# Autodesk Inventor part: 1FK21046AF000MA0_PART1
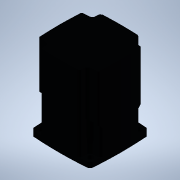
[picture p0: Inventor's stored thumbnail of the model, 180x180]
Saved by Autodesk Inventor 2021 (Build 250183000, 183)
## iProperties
Created: 2025-04
Part Number: 1FK21046AF000MA0_PART1
Material: Generic
Catalog Web Link: www.3dfindit.com
Description: -Servo synchronous motor
Document SubType Name: Modeling
Designer: psAdmin
Mass: 575.884 g
Surface Area: 489.738 cm^2
Volume: 575.884 cm^3
Density: 1 g/cm^3
Appearance: PSOLRGB-176-176-176
Category: PARTsolutions
Title: 1FK21046AF000MA0_PART1
Author: Cadenas PARTsolutions
Comments: Servo synchronous motor
Sending System: PARTsolutions
Preprocessor: ST-DEVELOPER v19.3
PSOL_IDENT_0: {$CADENAS_DATA/23d-libs/siemens_ag/_cat_/1c/1f/1fk21046af000ma0.prj},213 {VTYP=3D},{NB=1FK21046AF000
PSOL_IDENT_1: MA0_PART1},{LINA=1FK21046AF000MA0_PART1},{NN=1FK21046AF000MA0_PART1},{NOPRJ=TRUE},{DATE=19.08.2025 1
PSOL_IDENT_2: 4:00:28},{GEOMDATE=30.07.2025 02:02:08},{VERSION=},{LINEID=10},{WBVAR=},{WBNUMERIC=}  {NB=1FK21046AF
PSOL_IDENT_3: 000MA0_PART1},{LINA=1FK21046AF000MA0_PART1},{KT=DUMMY},{PREVIEW=../../../_pool_/cb/72/p_d211_xx_0043
PSOL_IDENT_4: 4j.png},{DESCSHORT=SIMOTICS S-1FK2 HD, SINAMICS S210 3AC 400V-480V, 3.2 Nm, 3000 rpm},{DESCLONG=SIMO
PSOL_IDENT_5: TICS S-1FK2 HD servo motor M0=3.2 Nm; PN = 1 kW at nN=3000 rpm (380-480 V); PN = 0.5 kW at nN=1500 r
PSOL_IDENT_6: pm (200-240 V); degree of protection IP64; cylindrical shaft D19x40mm; absolute encoder 22-bit + 12-
PSOL_IDENT_7: bit multiturn (encoder AM22DQC); with OCC interface; plug size M17, rotatable; SIMOTICS S-1FK2 servo
PSOL_IDENT_8: motorfor a wide range of uses in industrial environments. SIMOTICS S‑1FK2 servomotors are compact sy
PSOL_IDENT_9: nchronous motors with a high dynamic performance that set themselves apart as a result of their high
PSOL_IDENT_10: power density, degree of protection and overload capability. The motors are available in two varian
PSOL_IDENT_11: ts: as High Dynamic variant (highest dynamic performance as a result of the low intrinsic moment of
PSOL_IDENT_12: inertia for applications demanding a high dynamic performance with low moved masses) - and as Compac
PSOL_IDENT_13: t variant (precise and stable closed-loop control for medium up to large moved masses as a result of
PSOL_IDENT_14: a medium intrinsic moment of inertia). SIMOTICSS‑1FK2 servomotors fully exploit their strengths in
PSOL_IDENT_15: a system with the SINAMICSS210 frequency converter and simple connection using the one cable connect
PSOL_IDENT_16: ion (OCC). Advantages include the short control and positioning times, fast and precise correction o
PSOL_IDENT_17: f disturbing quantities as well as stable control with a high dynamic performance. The servo motors
PSOL_IDENT_18: can be configured to address a wide range of requirements. For example with and without holding brak
PSOL_IDENT_19: e, IP64 or IP65 degree of protection, singleturn or multiturn absolute encoders - to name just a few
PSOL_IDENT_20: . Further, the servomotors are available in different shaft heights extending from 20 to 100. A shaf
PSOL_IDENT_21: t sealing ring is available to achieve an IP65 degree of protection and for subsequent mounting at t
PSOL_IDENT_22: he motor or as spare part. SIMOTICS - the optimum motor for each and every motion control applicatio
PSOL_IDENT_23: n.},{INTNO=195125049666},{SUPPLIERALTNO=1FK2104-6AF00-0MA0},{MANUID=1FK21046AF000MA0},{MANUNAME=Siem
PSOL_IDENT_24: ens},{MANUTYPEDESC=Synchronous motor 1FK2-HD 3.2 NM},{AAU732=SIMOTICS},{AAO057=S-1FK2},{AAU734=SIMOT
PSOL_IDENT_25: ICS S-1FK2 HD servo motor M0=3.2 Nm; PN = 1 kW at nN=3000 rpm (380-480 V); PN = 0.5 kW at nN=1500 rp
PSOL_IDENT_26: m (200-240 V); degree of protection IP64; cylindrical shaft D19x40mm; absolute encoder 22-bit + 12-b
PSOL_IDENT_27: it multiturn (encoder AM22DQC); with OCC interface; plug size M17, rotatable;},{AAW338=Synchronous m
PSOL_IDENT_28: otor 1FK2-HD 3.2 NM},{AAO742=SIMOTICS},{AAO663=4042948694374},{NOCUPEROU=1},{PRICEQUANTITY=1},{QUANT
PSOL_IDENT_29: ITYMIN=1},{QUANTITYINT=1},{CTN=85015220},{COO=DE},{AAO676=1FK2104-6AF00-0MA0},{AAO677=Siemens AG},{O
PSOL_IDENT_30: RDERUNIT=C62},{CONTENTUNIT=C62}
NB: 1FK21046AF000MA0_PART1
NT: Servo synchronous motor
NBSYN: $MANUID._PART1
LINA: 1FK21046AF000MA0_PART1
CATALOG: SIEMENS
PREVIEW: ../../../_pool_/cb/72/p_d211_xx_00434j.png
DESCSHORT: SIMOTICS S-1FK2 HD, SINAMICS S210 3AC 400V-480V, 3.2 Nm, 3000 rpm
DESCLONG: SIMOTICS S-1FK2 HD servo motor M0=3.2 Nm; PN = 1 kW at nN=3000 rpm (380-480 V); PN = 0.5 kW at nN=1500 rpm (200-240 V); degree of protection IP64; cylindrical s
INTNO: 195125049666
SUPPLIERALTNO: 1FK2104-6AF00-0MA0
MANUID: 1FK21046AF000MA0
MANUNAME: Siemens
MANUTYPEDESC: Synchronous motor 1FK2-HD 3.2 NM
AAU732: SIMOTICS
AAO057: S-1FK2
AAU734: SIMOTICS S-1FK2 HD servo motor M0=3.2 Nm; PN = 1 kW at nN=3000 rpm (380-480 V); PN = 0.5 kW at nN=1500 rpm (200-240 V); degree of protection IP64; cylindrical s
AAW338: Synchronous motor 1FK2-HD 3.2 NM
AAO742: SIMOTICS
AAO663: 4042948694374.0
NOCUPEROU: 1
PRICEQUANTITY: 1
QUANTITYMIN: 1
QUANTITYINT: 1
CTN: 85015220
COO: DE
ARTICLENO: 1FK21046AF000MA0_PART1
BOMINFO: 1FK21046AF000MA0_PART1
CREATOR: CADENAS GmbH
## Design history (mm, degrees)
feature "2025_04_17_15_39_11_0268"
node "ECLASS_CAX_IMPORTER_001_CP_0_XY"
node "ECLASS_CAX_IMPORTER_001_CP_0_YZ"
node "ECLASS_CAX_IMPORTER_001_CP_0_ZX"
node "ECLASS_CAX_IMPORTER_001_CP_0_X"
node "ECLASS_CAX_IMPORTER_001_CP_0_Y"
node "ECLASS_CAX_IMPORTER_001_CP_0_Z"
node "ECLASS_CAX_IMPORTER_001_CP_0_Center"
node "ECLASS_CAX_IMPORTER_001_CP_1_XY"
node "ECLASS_CAX_IMPORTER_001_CP_1_YZ"
node "ECLASS_CAX_IMPORTER_001_CP_1_ZX"
node "ECLASS_CAX_IMPORTER_001_CP_1_X"
node "ECLASS_CAX_IMPORTER_001_CP_1_Y"
node "ECLASS_CAX_IMPORTER_001_CP_1_Z"
node "ECLASS_CAX_IMPORTER_001_CP_1_Center"
body "Solid1"
